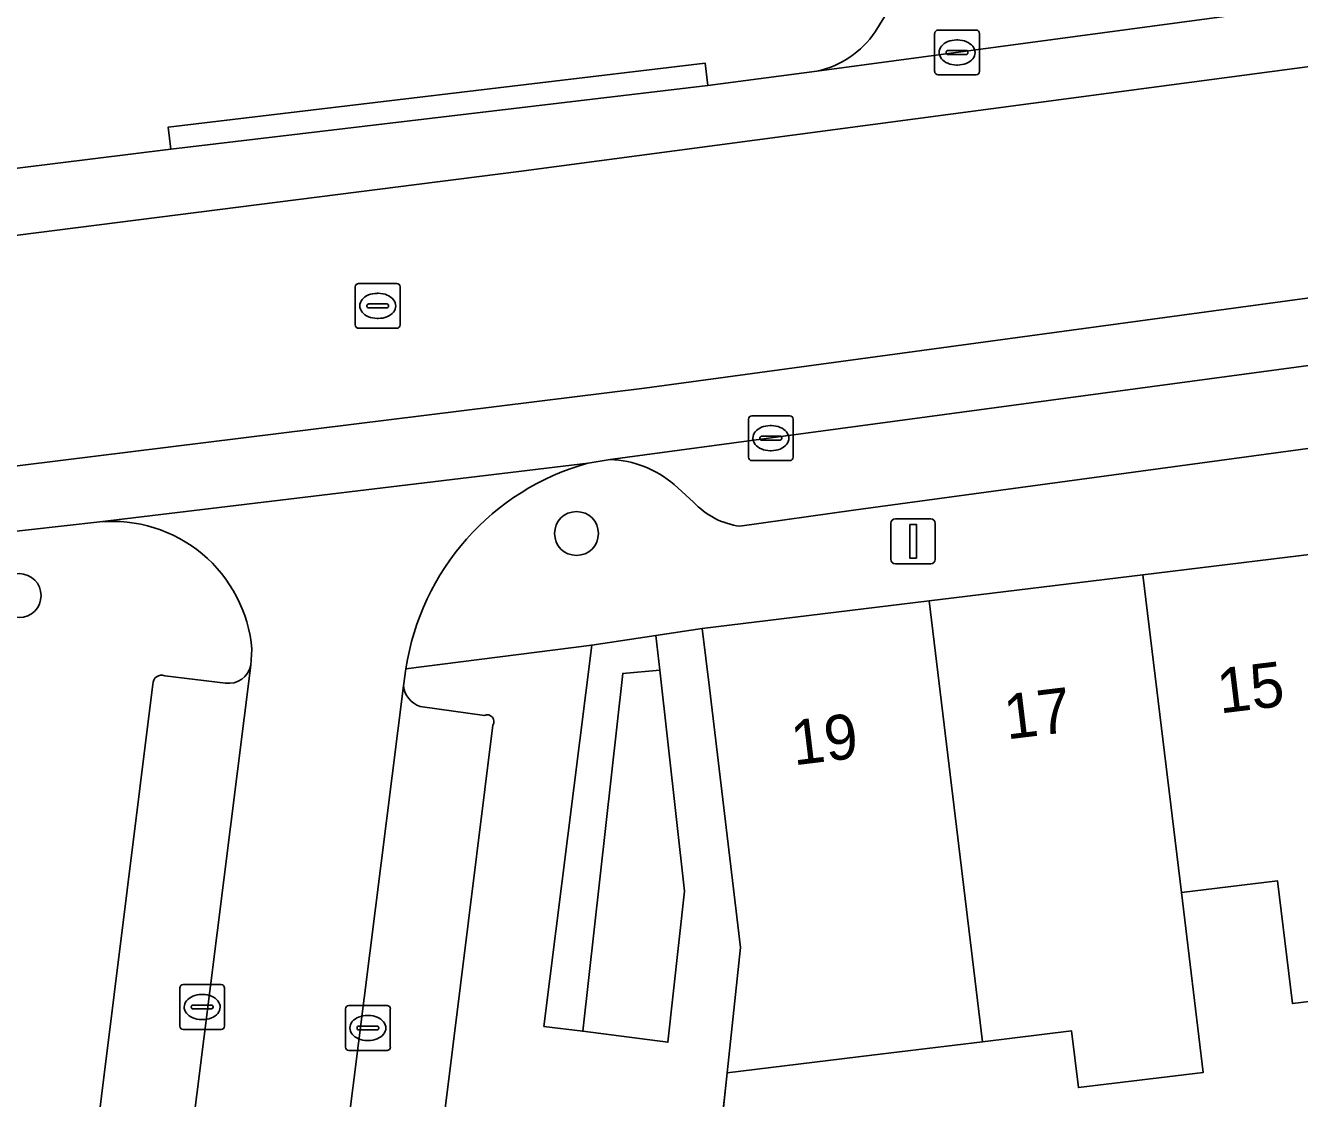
# Model space of a CAD drawing. Extents: x 162172 to 163187, y 382874 to 383685.
# Drawn here: x 162849.67 to 162878.09, y 383256.98 to 383280.9 of the extents above; entities that cross this region are included whole.
import ezdxf

# ---------------------------------------------------------------- set-up
doc = ezdxf.new("R2010")
doc.units = 0
for name, color, linetype in [('IMGEO_Boom', 7, 'Continuous'), ('IMGEO_Erf', 7, 'Continuous'), ('IMGEO_Groenvoorziening', 7, 'Continuous'), ('IMGEO_Haag', 7, 'Continuous'), ('IMGEO_Kolk', 7, 'Continuous'), ('IMGEO_Lichtmast', 7, 'Continuous'), ('IMGEO_Muur', 7, 'Continuous'), ('IMGEO_Pand', 7, 'Continuous'), ('IMGEO_Pand_nummerreeks', 7, 'Continuous'), ('IMGEO_Parkeervlak_open', 7, 'Continuous'), ('IMGEO_Rijbaan_lokaal_gesloten', 7, 'Continuous'), ('IMGEO_Rijbaan_lokaal_open', 7, 'Continuous'), ('IMGEO_Rioolput', 7, 'Continuous'), ('IMGEO_Voetpad_open', 7, 'Continuous')]:
    doc.layers.add(name, color=color, linetype=linetype)

msp = doc.modelspace()

# ---------------------------------------------------------------- linework, layer by layer
at = {"layer": 'IMGEO_Boom'}
for centre in [(162861.962, 383269.572), (162849.533, 383268.189)]:
    msp.add_circle(centre, 0.489, dxfattribs=at)
at = {"layer": 'IMGEO_Erf'}
msp.add_lwpolyline([(162880.533, 383259.411), (162877.927, 383259.092), (162877.594, 383261.833), (162875.451, 383261.573), (162875.938, 383257.56), (162873.154, 383257.223), (162873.001, 383258.483), (162871.019, 383258.243), (162868.549, 383257.943), (162865.321, 383257.551), (162865.176, 383256.149), (162864.457, 383249.193), (162873.118, 383248.199), (162876.605, 383247.799), (162876.269, 383244.868), (162878.461, 383244.628)], dxfattribs=at)
at = {"layer": 'IMGEO_Groenvoorziening'}
for points in [[(162863.82, 383266.526), (162863.733, 383267.302), (162862.302, 383267.086), (162861.237, 383258.586), (162862.1, 383258.476), (162862.992, 383266.453)], [(162863.82, 383266.526), (162862.992, 383266.453), (162862.1, 383258.476), (162864.001, 383258.233), (162864.373, 383261.597)]]:
    msp.add_lwpolyline(points, close=True, dxfattribs=at)
at = {"layer": 'IMGEO_Haag'}
msp.add_lwpolyline([(162861.237, 383258.586), (162862.1, 383258.476), (162862.992, 383266.453), (162863.82, 383266.526), (162863.733, 383267.302), (162862.302, 383267.086)], close=True, dxfattribs=at)
at = {"layer": 'IMGEO_Kolk'}
for p, q in [((162869.949, 383279.868), (162869.949, 383280.72)), ((162870.024, 383280.794), (162870.876, 383280.794)), ((162870.95, 383280.72), (162870.95, 383279.868)), ((162870.437, 383280.574), (162870.462, 383280.574)), ((162870.208, 383280.288), (162870.208, 383280.3)), ((162870.646, 383280.251), (162870.248, 383280.251)), ((162870.251, 383280.337), (162870.649, 383280.337)), ((162870.692, 383280.3), (162870.692, 383280.288)), ((162870.46, 383280.014), (162870.435, 383280.014)), ((162870.876, 383279.794), (162870.024, 383279.794)), ((162865.87, 383272.197), (162866.722, 383272.197)), ((162865.795, 383271.271), (162865.795, 383272.123)), ((162866.283, 383271.977), (162866.308, 383271.977)), ((162866.796, 383272.123), (162866.796, 383271.271)), ((162866.054, 383271.691), (162866.054, 383271.703)), ((162866.492, 383271.654), (162866.094, 383271.654)), ((162866.097, 383271.74), (162866.495, 383271.74)), ((162866.538, 383271.703), (162866.538, 383271.691)), ((162866.306, 383271.417), (162866.281, 383271.417)), ((162866.722, 383271.197), (162865.87, 383271.197)), ((162853.113, 383258.59), (162853.113, 383259.442)), ((162853.188, 383259.516), (162854.04, 383259.516)), ((162854.114, 383259.442), (162854.114, 383258.59)), ((162853.601, 383259.296), (162853.626, 383259.296)), ((162853.372, 383259.01), (162853.372, 383259.022)), ((162853.81, 383258.973), (162853.412, 383258.973)), ((162853.415, 383259.059), (162853.813, 383259.059)), ((162853.856, 383259.022), (162853.856, 383259.01)), ((162856.809, 383258.124), (162856.809, 383258.976)), ((162856.884, 383259.05), (162857.736, 383259.05)), ((162857.81, 383258.976), (162857.81, 383258.124)), ((162853.624, 383258.736), (162853.599, 383258.736)), ((162857.068, 383258.544), (162857.068, 383258.556)), ((162857.111, 383258.593), (162857.509, 383258.593)), ((162857.297, 383258.83), (162857.322, 383258.83)), ((162857.552, 383258.556), (162857.552, 383258.544)), ((162854.04, 383258.516), (162853.188, 383258.516)), ((162857.506, 383258.507), (162857.108, 383258.507)), ((162857.32, 383258.27), (162857.295, 383258.27)), ((162857.736, 383258.05), (162856.884, 383258.05))]:
    msp.add_line(p, q, dxfattribs=at)
for points in [[(162869.949, 383279.868), (162869.949, 383280.72)], [(162870.024, 383280.794), (162870.876, 383280.794)], [(162870.95, 383280.72), (162870.95, 383279.868)], [(162870.876, 383279.794), (162870.024, 383279.794)], [(162865.87, 383272.197), (162866.722, 383272.197)], [(162865.795, 383271.271), (162865.795, 383272.123)], [(162866.796, 383272.123), (162866.796, 383271.271)], [(162866.722, 383271.197), (162865.87, 383271.197)], [(162853.113, 383258.59), (162853.113, 383259.442)], [(162853.188, 383259.516), (162854.04, 383259.516)], [(162854.114, 383259.442), (162854.114, 383258.59)], [(162856.809, 383258.124), (162856.809, 383258.976)], [(162856.884, 383259.05), (162857.736, 383259.05)], [(162857.81, 383258.976), (162857.81, 383258.124)], [(162854.04, 383258.516), (162853.188, 383258.516)], [(162857.736, 383258.05), (162856.884, 383258.05)]]:
    msp.add_lwpolyline(points, dxfattribs=at)
for centre, radius, start, end in [((162870.026, 383280.718), 0.0765, 91.552, 178.448), ((162870.026, 383280.718), 0.0765, 91.552, 178.448), ((162870.874, 383280.718), 0.0765, 1.552, 88.448), ((162870.874, 383280.718), 0.0765, 1.552, 88.448), ((162870.248, 383280.297), 0.0403, 85.8775, 175.7526), ((162870.245, 383280.287), 0.0366, 178.938, 274.7102), ((162870.649, 383280.294), 0.043, 264.8664, 352.4533), ((162870.653, 383280.299), 0.0386, 1.7309, 96.639), ((162870.026, 383279.87), 0.0765, 181.552, 268.448), ((162870.026, 383279.87), 0.0765, 181.552, 268.448), ((162870.874, 383279.87), 0.0765, 271.552, 358.448), ((162870.874, 383279.87), 0.0765, 271.552, 358.448), ((162865.872, 383272.121), 0.0765, 91.552, 178.448), ((162865.872, 383272.121), 0.0765, 91.552, 178.448), ((162866.72, 383272.121), 0.0765, 1.552, 88.448), ((162866.72, 383272.121), 0.0765, 1.552, 88.448), ((162866.094, 383271.7), 0.0403, 85.8775, 175.7526), ((162866.091, 383271.69), 0.0366, 178.938, 274.7102), ((162866.495, 383271.697), 0.043, 264.8664, 352.4533), ((162866.499, 383271.702), 0.0386, 1.7309, 96.639), ((162865.872, 383271.273), 0.0765, 181.552, 268.448), ((162865.872, 383271.273), 0.0765, 181.552, 268.448), ((162866.72, 383271.273), 0.0765, 271.552, 358.448), ((162866.72, 383271.273), 0.0765, 271.552, 358.448), ((162853.19, 383259.44), 0.0765, 91.552, 178.448), ((162853.19, 383259.44), 0.0765, 91.552, 178.448), ((162854.038, 383259.44), 0.0765, 1.552, 88.448), ((162854.038, 383259.44), 0.0765, 1.552, 88.448), ((162853.412, 383259.019), 0.0403, 85.8775, 175.7526), ((162853.409, 383259.009), 0.0366, 178.938, 274.7102), ((162853.813, 383259.016), 0.043, 264.8664, 352.4533), ((162853.817, 383259.021), 0.0386, 1.7309, 96.639), ((162856.886, 383258.974), 0.0765, 91.552, 178.448), ((162856.886, 383258.974), 0.0765, 91.552, 178.448), ((162857.734, 383258.974), 0.0765, 1.552, 88.448), ((162857.734, 383258.974), 0.0765, 1.552, 88.448), ((162853.19, 383258.592), 0.0765, 181.552, 268.448), ((162853.19, 383258.592), 0.0765, 181.552, 268.448), ((162854.038, 383258.592), 0.0765, 271.552, 358.448), ((162854.038, 383258.592), 0.0765, 271.552, 358.448), ((162857.108, 383258.553), 0.0403, 85.8775, 175.7526), ((162857.513, 383258.555), 0.0386, 1.7309, 96.639), ((162857.105, 383258.543), 0.0366, 178.938, 274.7102), ((162857.509, 383258.55), 0.043, 264.8664, 352.4533), ((162856.886, 383258.126), 0.0765, 181.552, 268.448), ((162856.886, 383258.126), 0.0765, 181.552, 268.448), ((162857.734, 383258.126), 0.0765, 271.552, 358.448), ((162857.734, 383258.126), 0.0765, 271.552, 358.448)]:
    msp.add_arc(centre, radius, start, end, dxfattribs=at)
for centre, major_axis, ratio, start_param, end_param in [((162870.436, 383280.294), (-0.387, 0.002), 0.722429, 4.712389, 7.853982), ((162870.461, 383280.294), (-0.39, 0.002), 0.717154, 1.570796, 4.712389), ((162866.282, 383271.697), (-0.387, 0.002), 0.722429, 4.712389, 7.853982), ((162866.307, 383271.697), (-0.39, 0.002), 0.717154, 1.570796, 4.712389), ((162853.6, 383259.016), (-0.387, 0.002), 0.722429, 4.712389, 7.853982), ((162853.625, 383259.016), (-0.39, 0.002), 0.717154, 1.570796, 4.712389), ((162857.296, 383258.55), (-0.387, 0.002), 0.722429, 4.712389, 7.853982), ((162857.321, 383258.55), (-0.39, 0.002), 0.717154, 1.570796, 4.712389)]:
    msp.add_ellipse(centre, major_axis=major_axis, ratio=ratio, start_param=start_param, end_param=end_param, dxfattribs=at)
at = {"layer": 'IMGEO_Lichtmast'}
for p, q in [((162868.973, 383268.998), (162868.973, 383269.798)), ((162868.973, 383269.798), (162868.973, 383268.998)), ((162869.073, 383269.898), (162869.863, 383269.898)), ((162869.863, 383269.898), (162869.073, 383269.898)), ((162869.963, 383269.798), (162869.963, 383268.998)), ((162869.963, 383268.998), (162869.963, 383269.798)), ((162869.863, 383268.898), (162869.073, 383268.898)), ((162869.073, 383268.898), (162869.863, 383268.898))]:
    msp.add_line(p, q, dxfattribs=at)
msp.add_lwpolyline([(162869.393, 383269.773), (162869.543, 383269.773), (162869.543, 383269.023), (162869.393, 383269.023), (162869.393, 383269.773)], dxfattribs=at)
for centre, start, end in [((162869.073, 383269.798), 90, 180), ((162869.073, 383269.798), 90, 180), ((162869.863, 383269.798), 0, 90), ((162869.863, 383269.798), 360, 90), ((162869.073, 383268.998), 180, 270), ((162869.073, 383268.998), 180, 270), ((162869.863, 383268.998), 270, 0), ((162869.863, 383268.998), 270, 0)]:
    msp.add_arc(centre, 0.1, start, end, dxfattribs=at)
at = {"layer": 'IMGEO_Muur'}
msp.add_lwpolyline([(162865.321, 383257.551), (162865.212, 383256.528)], dxfattribs=at)
at = {"layer": 'IMGEO_Pand'}
for points in [[(162880.533, 383259.411), (162879.343, 383269.231), (162874.594, 383268.653), (162875.451, 383261.573), (162877.594, 383261.833), (162877.927, 383259.092)], [(162871.019, 383258.243), (162873.001, 383258.483), (162873.154, 383257.223), (162875.938, 383257.56), (162875.451, 383261.573), (162874.594, 383268.653), (162869.828, 383268.074)], [(162871.019, 383258.243), (162869.828, 383268.074), (162864.768, 383267.458), (162864.926, 383266.133), (162865.618, 383260.347), (162865.321, 383257.551), (162868.549, 383257.943)]]:
    msp.add_lwpolyline(points, close=True, dxfattribs=at)
at = {"layer": 'IMGEO_Parkeervlak_open'}
for points in [[(162867.323, 383279.879), (162910.202, 383285.636)], [(162869.141, 383281.604), (162868.622, 383280.753)], [(162912.085, 383277.862), (162862.712, 383271.218)], [(162865.608, 383269.734), (162868.141, 383270.092), (162909.604, 383275.716)], [(162864.138, 383270.664), (162864.573, 383270.274)], [(162842.882, 383172.464), (162843.478, 383177.192), (162843.862, 383180.235), (162849.781, 383227.424), (162850.197, 383230.839), (162854.699, 383266.635)], [(162854.134, 383266.238), (162852.78, 383266.399)], [(162852.517, 383266.21), (162840.771, 383172.051)], [(162858.101, 383266.173), (162853.597, 383230.421), (162853.195, 383227.037), (162847.239, 383179.833), (162846.839, 383176.809), (162846.274, 383172.331)], [(162859.909, 383265.516), (162858.472, 383265.718)], [(162857.935, 383247.912), (162860.096, 383265.298)]]:
    msp.add_lwpolyline(points, dxfattribs=at)
for centre, radius, start, end in [((162866.887, 383281.929), 2.096, 281.9979, 325.8694), ((162862.652, 383268.952), 2.267, 49.0464, 88.4913), ((162865.834, 383271.43), 1.711, 222.4996, 262.3948), ((162854.207, 383266.734), 0.502, 261.5918, 348.5962), ((162852.705, 383266.226), 0.189, 66.6475, 184.7569), ((162858.642, 383266.235), 0.544, 186.5422, 251.8443), ((162859.972, 383265.381), 0.149, 326.3036, 114.9422)]:
    msp.add_arc(centre, radius, start, end, dxfattribs=at)
at = {"layer": 'IMGEO_Rijbaan_lokaal_gesloten'}
for points in [[(162902.89, 383283.254), (162860.673, 383277.644), (162837.383, 383274.682), (162792.751, 383269.305), (162780.522, 383267.902), (162777.64, 383267.669), (162775.303, 383267.747), (162773.512, 383268.136), (162770.629, 383268.838), (162768.371, 383269.773), (162766.423, 383271.253), (162759.102, 383279.436), (162751.245, 383288.934)], [(162751.245, 383288.934), (162759.102, 383279.436), (162766.423, 383271.253), (162768.371, 383269.773), (162770.629, 383268.838), (162773.512, 383268.136), (162775.303, 383267.747), (162777.64, 383267.669), (162780.522, 383267.902), (162792.751, 383269.305), (162837.383, 383274.682), (162860.673, 383277.644), (162902.89, 383283.254)], [(162918.71, 383286.762), (162915.158, 383286.298), (162910.833, 383285.724), (162910.202, 383285.636), (162867.323, 383279.879), (162864.893, 383279.559), (162852.915, 383278.136), (162849.496, 383277.716), (162779.577, 383269.28), (162779.14, 383269.227), (162778.108, 383269.171)], [(162746.988, 383284.773), (162754.973, 383275.848), (162761.671, 383268.445), (162764.865, 383265.64), (162770.006, 383263.146), (162774.835, 383262.367), (162778.262, 383262.289), (162808.407, 383266.029), (162835.747, 383269.38), (162863.477, 383272.809), (162911.477, 383279.327), (162911.844, 383279.376), (162920.076, 383280.478), (162919.326, 383285.358)], [(162927.187, 383281.43), (162920.076, 383280.478), (162911.844, 383279.376), (162911.477, 383279.327), (162863.477, 383272.809), (162835.747, 383269.38), (162808.407, 383266.029), (162778.262, 383262.289), (162774.835, 383262.367), (162770.006, 383263.146), (162764.865, 383265.64), (162761.671, 383268.445), (162754.973, 383275.848), (162746.988, 383284.773)], [(162775.63, 383260.847), (162781.571, 383261.396), (162786.414, 383262.022), (162787.483, 383262.198), (162790.095, 383262.473), (162819.027, 383265.957), (162822.009, 383266.344), (162848.142, 383269.478), (162851.329, 383269.83), (162862.219, 383271.142), (162862.712, 383271.218), (162912.085, 383277.862), (162912.638, 383277.916), (162924.452, 383279.503), (162929.847, 383280.24), (162930.976, 383280.432), (162932.962, 383280.637), (162934.995, 383280.773)]]:
    msp.add_lwpolyline(points, dxfattribs=at)
at = {"layer": 'IMGEO_Rijbaan_lokaal_open'}
for points in [[(162862.219, 383271.142), (162851.329, 383269.83)], [(162854.724, 383266.995), (162854.699, 383266.635), (162850.197, 383230.839), (162853.597, 383230.421), (162858.101, 383266.173), (162858.158, 383266.556)]]:
    msp.add_lwpolyline(points, dxfattribs=at)
for centre, radius, start, end in [((162863.736, 383265.707), 5.643, 105.6006, 171.3483), ((162851.613, 383266.72), 3.123, 5.0515, 95.2213)]:
    msp.add_arc(centre, radius, start, end, dxfattribs=at)
at = {"layer": 'IMGEO_Rioolput'}
for p, q in [((162857.029, 383274.22), (162857.029, 383275.072)), ((162857.104, 383275.146), (162857.956, 383275.146)), ((162858.03, 383275.072), (162858.03, 383274.22)), ((162857.517, 383274.926), (162857.542, 383274.926)), ((162857.288, 383274.64), (162857.288, 383274.652)), ((162857.726, 383274.603), (162857.328, 383274.603)), ((162857.331, 383274.689), (162857.729, 383274.689)), ((162857.772, 383274.652), (162857.772, 383274.64)), ((162857.54, 383274.366), (162857.515, 383274.366)), ((162857.956, 383274.146), (162857.104, 383274.146))]:
    msp.add_line(p, q, dxfattribs=at)
for points in [[(162857.029, 383274.22), (162857.029, 383275.072)], [(162857.104, 383275.146), (162857.956, 383275.146)], [(162858.03, 383275.072), (162858.03, 383274.22)], [(162857.956, 383274.146), (162857.104, 383274.146)]]:
    msp.add_lwpolyline(points, dxfattribs=at)
for centre, radius, start, end in [((162857.106, 383275.07), 0.0765, 91.552, 178.448), ((162857.106, 383275.07), 0.0765, 91.552, 178.448), ((162857.954, 383275.07), 0.0765, 1.552, 88.448), ((162857.954, 383275.07), 0.0765, 1.552, 88.448), ((162857.328, 383274.649), 0.0403, 85.8775, 175.7526), ((162857.325, 383274.639), 0.0366, 178.938, 274.7102), ((162857.729, 383274.646), 0.043, 264.8664, 352.4533), ((162857.733, 383274.651), 0.0386, 1.7309, 96.639), ((162857.106, 383274.222), 0.0765, 181.552, 268.448), ((162857.106, 383274.222), 0.0765, 181.552, 268.448), ((162857.954, 383274.222), 0.0765, 271.552, 358.448), ((162857.954, 383274.222), 0.0765, 271.552, 358.448)]:
    msp.add_arc(centre, radius, start, end, dxfattribs=at)
for centre, major_axis, ratio, start_param, end_param in [((162857.516, 383274.646), (-0.387, 0.002), 0.722429, 4.712389, 7.853982), ((162857.541, 383274.646), (-0.39, 0.002), 0.717154, 1.570796, 4.712389)]:
    msp.add_ellipse(centre, major_axis=major_axis, ratio=ratio, start_param=start_param, end_param=end_param, dxfattribs=at)
at = {"layer": 'IMGEO_Voetpad_open'}
for points in [[(162868.622, 383280.753), (162869.141, 383281.604)], [(162849.496, 383277.716), (162852.915, 383278.136), (162852.857, 383278.632), (162864.835, 383280.055), (162864.893, 383279.559), (162867.323, 383279.879)], [(162909.604, 383275.716), (162868.141, 383270.092), (162865.608, 383269.734)], [(162862.712, 383271.218), (162862.219, 383271.142)], [(162858.158, 383266.556), (162862.302, 383267.086), (162863.733, 383267.302), (162864.768, 383267.458), (162869.828, 383268.074), (162874.594, 383268.653), (162879.343, 383269.231), (162884.194, 383269.821), (162889.01, 383270.407), (162893.42, 383270.943)], [(162864.573, 383270.274), (162864.138, 383270.664)], [(162851.329, 383269.83), (162848.142, 383269.478)], [(162860.37, 383245.339), (162863.979, 383244.938), (162864.12, 383246.262), (162864.138, 383246.421), (162860.62, 383246.857), (162859.777, 383246.962), (162861.036, 383256.654), (162861.888, 383256.55), (162865.176, 383256.149), (162865.321, 383257.551), (162865.618, 383260.347), (162864.926, 383266.133), (162864.768, 383267.458), (162863.733, 383267.302), (162863.82, 383266.526), (162864.373, 383261.597), (162864.001, 383258.233), (162862.1, 383258.476), (162861.237, 383258.586), (162862.302, 383267.086), (162858.158, 383266.556), (162858.101, 383266.173)], [(162854.699, 383266.635), (162854.724, 383266.995)], [(162852.78, 383266.399), (162854.134, 383266.238)], [(162840.771, 383172.051), (162852.517, 383266.21)], [(162858.472, 383265.718), (162859.909, 383265.516)], [(162860.096, 383265.298), (162857.935, 383247.912)]]:
    msp.add_lwpolyline(points, dxfattribs=at)
msp.add_lwpolyline([(162852.915, 383278.136), (162864.893, 383279.559), (162864.835, 383280.055), (162852.857, 383278.632)], close=True, dxfattribs=at)
for centre, radius, start, end in [((162866.887, 383281.929), 2.096, 281.9979, 325.8694), ((162863.736, 383265.707), 5.643, 105.6006, 171.3483), ((162862.652, 383268.952), 2.267, 49.0464, 88.4913), ((162865.834, 383271.43), 1.711, 222.4996, 262.3948), ((162851.613, 383266.72), 3.123, 5.0515, 95.2213), ((162854.207, 383266.734), 0.502, 261.5918, 348.5962), ((162852.705, 383266.226), 0.189, 66.6475, 184.7569), ((162858.642, 383266.235), 0.544, 186.5422, 251.8443), ((162859.972, 383265.381), 0.149, 326.3036, 114.9422)]:
    msp.add_arc(centre, radius, start, end, dxfattribs=at)

# ---------------------------------------------------------------- texts
at = {"layer": 'IMGEO_Pand_nummerreeks'}
for s, p in [('15', (162876.311, 383265.558)), ('17', (162871.56, 383264.98)), ('19', (162866.809, 383264.402))]:
    msp.add_text(s, height=1, rotation=6.9358, dxfattribs=at).set_placement(p)

doc.saveas('drawing.dxf')
